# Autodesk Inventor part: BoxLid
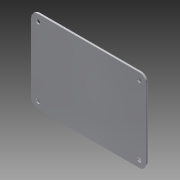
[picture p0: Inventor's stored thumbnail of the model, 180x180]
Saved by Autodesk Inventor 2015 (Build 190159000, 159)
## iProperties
Created: 2014-07
Part Number: BoxLid
Material: Aluminum 6061
Document SubType Name: Modeling
Designer: Gavin
Density: 2.7 g/cm^3
Appearance: Aluminum - Flat
Author: Gavin
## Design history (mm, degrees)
derived "BoxSketch.ipt"
  sketch "Sketch1"
    geometry: L1 (-135, -69.5)-(-139, -69.5) reference; L2 (-147.5, -61)-(-147.5, 61) reference; L3 (-139, 69.5)-(-135, 69.5) reference; L4 (-129.5, 75)-(-129.5, 79) reference; L5 (-121, 87.5)-(121, 87.5) reference; L6 (129.5, 79)-(129.5, 75) reference; L7 (135, 69.5)-(139, 69.5) reference; L8 (147.5, 61)-(147.5, -61) reference; L9 (139, -69.5)-(135, -69.5) reference; L10 (129.5, -75)-(129.5, -79) reference; L11 (121, -82)-(-121, -82) reference; L12 (-142, -61)-(-142, 61) reference; L13 (-121, 82)-(121, 82) reference; L14 (142, 61)-(142, -61) reference; L15 (124, -79)-(124, -75) reference; L16 (135, -64)-(139, -64) reference; L17 (0, -90)-(0, 90) reference; L18 (150, 0)-(-150, 0) reference; L19 (-124, -79)-(-124, -75) reference; L20 (-135, -64)-(-139, -64) reference; L21 (124, 79)-(124, 75) reference; L22 (135, 64)-(139, 64) reference; L23 (-124, 79)-(-124, 75) reference; L24 (-135, 64)-(-139, 64) reference; L25 (-121, -84.5)-(121, -84.5) reference; L26 (126.5, -79)-(126.5, -75) reference; L27 (135, -66.5)-(139, -66.5) reference; L28 (144.5, -61)-(144.5, 61) reference; L29 (139, 66.5)-(135, 66.5) reference; L30 (126.5, 75)-(126.5, 79) reference; L31 (121, 84.5)-(-121, 84.5) reference; L32 (-126.5, 79)-(-126.5, 75) reference; L33 (-135, 66.5)-(-139, 66.5) reference; L34 (-144.5, 61)-(-144.5, -61) reference; L35 (-139, -66.5)-(-135, -66.5) reference; L36 (-126.5, -75)-(-126.5, -79) reference; L37 (121, -87.5)-(-121, -87.5) reference; L38 (-129.5, -79)-(-129.5, -75) reference; L39 (135, 90)-(-135, 90) reference; L40 (-150, 75)-(-150, -75) reference; L41 (-135, -90)-(135, -90) reference; L42 (150, -75)-(150, 75) reference; L43 (150, 90)-(-150, -90) reference; L44 (-150, 90)-(150, -90) reference; C1 r 3 at (135, -75) reference; C2 r 3 at (-135, -75) reference; C3 r 3 at (135, 75) reference; C4 r 3 at (-135, 75) reference; A1 r 8.5 centre (-139, -61) between (-147.5, -61) and (-139, -69.5) reference; A2 r 8.5 centre (-139, 61) between (-139, 69.5) and (-147.5, 61) reference; A3 r 5.5 centre (-135, 75) between (-135, 69.5) and (-129.5, 75) reference; A4 r 8.5 centre (-121, 79) between (-121, 87.5) and (-129.5, 79) reference; A5 r 8.5 centre (121, 79) between (129.5, 79) and (121, 87.5) reference; A6 r 5.5 centre (135, 75) between (129.5, 75) and (135, 69.5) reference; A7 r 8.5 centre (139, 61) between (147.5, 61) and (139, 69.5) reference; A8 r 8.5 centre (139, -61) between (139, -69.5) and (147.5, -61) reference; A9 r 5.5 centre (135, -75) between (135, -69.5) and (129.5, -75) reference; A10 r 8.5 centre (121, -79) between (121, -87.5) and (129.5, -79) reference; A11 r 15 centre (-135, 75) between (-135, 90) and (-150, 75) reference; A12 r 11 centre (135, -75) between (135, -64) and (124, -75) reference; A13 r 3 centre (121, -79) between (121, -82) and (124, -79) reference; A14 r 3 centre (139, -61) between (139, -64) and (142, -61) reference; A15 r 11 centre (-135, -75) between (-124, -75) and (-135, -64) reference; A16 r 3 centre (-121, -79) between (-124, -79) and (-121, -82) reference; A17 r 3 centre (-139, -61) between (-142, -61) and (-139, -64) reference; A18 r 11 centre (135, 75) between (124, 75) and (135, 64) reference; A19 r 3 centre (121, 79) between (124, 79) and (121, 82) reference; A20 r 3 centre (139, 61) between (142, 61) and (139, 64) reference; A21 r 3 centre (-121, 79) between (-121, 82) and (-124, 79) reference; A22 r 11 centre (-135, 75) between (-135, 64) and (-124, 75) reference; A23 r 3 centre (-139, 61) between (-139, 64) and (-142, 61) reference; A24 r 5.5 centre (121, -79) between (121, -84.5) and (126.5, -79) reference; A25 r 8.5 centre (135, -75) between (135, -66.5) and (126.5, -75) reference; A26 r 5.5 centre (139, -61) between (139, -66.5) and (144.5, -61) reference; A27 r 5.5 centre (139, 61) between (144.5, 61) and (139, 66.5) reference; A28 r 8.5 centre (135, 75) between (126.5, 75) and (135, 66.5) reference; A29 r 5.5 centre (121, 79) between (126.5, 79) and (121, 84.5) reference; A30 r 5.5 centre (-121, 79) between (-121, 84.5) and (-126.5, 79) reference; A31 r 8.5 centre (-135, 75) between (-135, 66.5) and (-126.5, 75) reference; A32 r 5.5 centre (-139, 61) between (-139, 66.5) and (-144.5, 61) reference; A33 r 5.5 centre (-139, -61) between (-144.5, -61) and (-139, -66.5) reference; A34 r 8.5 centre (-135, -75) between (-126.5, -75) and (-135, -66.5) reference; A35 r 5.5 centre (-121, -79) between (-126.5, -79) and (-121, -84.5) reference; A36 r 8.5 centre (-121, -79) between (-129.5, -79) and (-121, -87.5) reference; A37 r 5.5 centre (-135, -75) between (-129.5, -75) and (-135, -69.5) reference; A38 r 15 centre (135, -75) between (135, -90) and (150, -75) reference; A39 r 15 centre (-135, -75) between (-150, -75) and (-135, -90) reference; A40 r 15 centre (135, 75) between (150, 75) and (135, 90) reference; 1 further point
extrude "Extrusion1" new body sketch "Sketch1" distance "d1" = 6; taper "d2" = -3 deg
sketch "Sketch2"
  geometry: C1 r 3 at (0, -164.686) reference; C2 r 3 at (270, -164.686) reference; C3 r 3 at (270, -14.686) reference; C4 r 3 at (0, -14.686) reference; 1 further point
hole "Hole1" sketch "Sketch2" at (270, -14.686), (270, -164.686), (0, -14.686), (0, -164.686) diameter "d3" = 9; stored, may be unused: countersink angle "d7" = 90 deg, drill point angle "d9" = 118 deg; dims "d4" = 6, "d5" = 17.3, "d6" = 2, "d8" = 8
fillet "Fillet1" dims "d10" = 3
body "Solid1"
